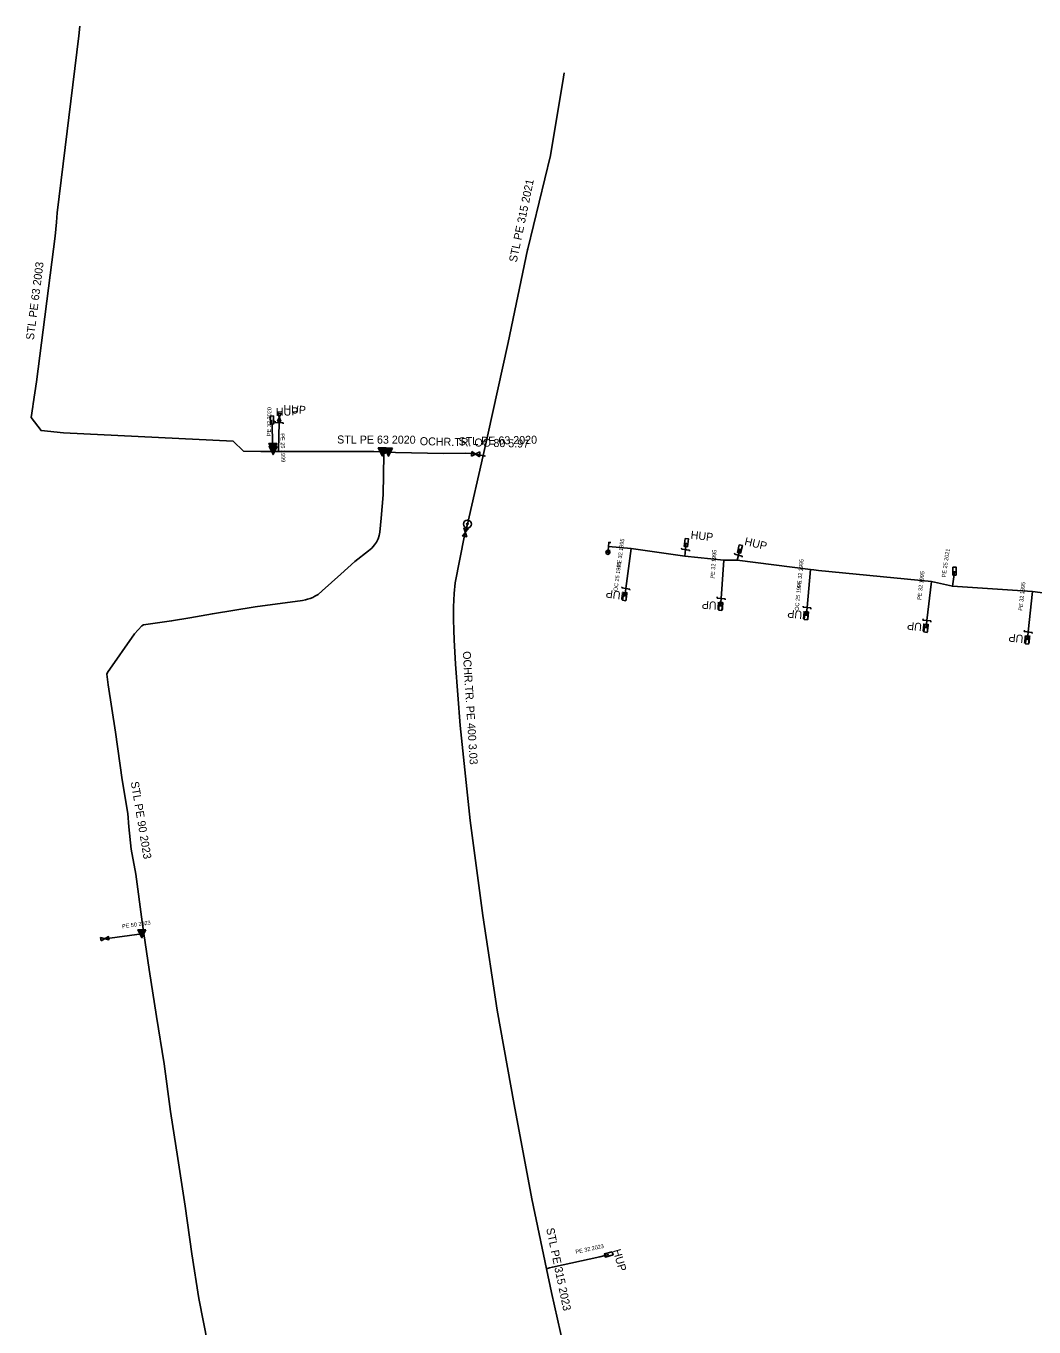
# Model space of a CAD drawing. Extents: x -745298 to -745026, y -1052719 to -1052281.
# Drawn here: x -745298.2 to -745172.2, y -1052443.7 to -1052281.1 of the extents above; entities that cross this region are included whole.
import ezdxf

# ---------------------------------------------------------------- set-up
doc = ezdxf.new("R2010")
doc.units = 0
for name, color, linetype in [('ST OP Chráni_ka - provoz', 7, 'Continuous'), ('ST Úsek p_ípojky - provoz', 7, 'Continuous'), ('ST Úsek plynovodu - provoz', 7, 'Continuous'), ('ST_HUP_22_23_popis', 7, 'Continuous'), ('ST_HUP_24_popis', 7, 'Continuous'), ('Vrstva 1', 7, 'Continuous')]:
    doc.layers.add(name, color=color, linetype=linetype)

msp = doc.modelspace()

# ---------------------------------------------------------------- linework, layer by layer
at = {"layer": 'ST OP Chráni_ka - provoz'}
for points in [[(-745264.93, -1052334.28), (-745254.68, -1052334.31)], [(-745251.97, -1052334.42), (-745246, -1052334.56)], [(-745244.67, -1052357.82), (-745244.48, -1052360.84)]]:
    msp.add_lwpolyline(points, dxfattribs=at)
at = {"layer": 'ST Úsek p_ípojky - provoz'}
for points in [[(-745267.31, -1052333.78), (-745267.43, -1052330.35)], [(-745266.6, -1052334.08), (-745266.54, -1052330.68), (-745266.54, -1052330.67)], [(-745266.54, -1052330.67), (-745266.51, -1052329.99)], [(-745267.29, -1052334.18), (-745267.31, -1052333.88), (-745267.31, -1052333.78)], [(-745266.61, -1052334.28), (-745266.6, -1052334.08)], [(-745267.29, -1052334.29), (-745267.29, -1052334.18)], [(-745222.53, -1052346.42), (-745223.2, -1052351.4)], [(-745215.82, -1052347.37), (-745215.73, -1052346.55)], [(-745215.73, -1052346.55), (-745215.63, -1052345.68)], [(-745209.11, -1052347.24), (-745208.93, -1052346.46)], [(-745210.94, -1052347.85), (-745211.28, -1052352.64)], [(-745209.26, -1052347.86), (-745209.11, -1052347.24)], [(-745200.09, -1052349.05), (-745200.54, -1052353.8)], [(-745182.37, -1052351.12), (-745182.11, -1052349.36), (-745182.11, -1052349.23)], [(-745223.2, -1052351.4), (-745223.33, -1052352.41)], [(-745184.99, -1052350.52), (-745185.56, -1052355.4)], [(-745172.36, -1052351.77), (-745172.89, -1052356.83)], [(-745211.28, -1052352.64), (-745211.35, -1052353.63)], [(-745200.54, -1052353.8), (-745200.64, -1052354.81)], [(-745185.56, -1052355.4), (-745185.67, -1052356.37)], [(-745172.89, -1052356.83), (-745172.99, -1052357.83)], [(-745283.69, -1052394.54), (-745288.32, -1052395.16)], [(-745283.43, -1052394.51), (-745283.69, -1052394.54)], [(-745233.12, -1052436.41), (-745232.75, -1052436.29), (-745232.36, -1052436.19), (-745226.44, -1052434.92), (-745225.32, -1052434.6)]]:
    msp.add_lwpolyline(points, dxfattribs=at)
at = {"layer": 'ST Úsek plynovodu - provoz'}
for points in [[(-745268.82, -1052334.29), (-745270.98, -1052334.26), (-745272.26, -1052333.01), (-745293.47, -1052331.95), (-745296.28, -1052331.68), (-745297.54, -1052330.05), (-745297.33, -1052328.67), (-745297.28, -1052328.34), (-745296.85, -1052325.57), (-745294.54, -1052307.4), (-745294.35, -1052305.63), (-745294.27, -1052304.46), (-745291.55, -1052282.34), (-745291.44, -1052281.13)], [(-745241.04, -1052334.8), (-745240.48, -1052332.37), (-745237.9, -1052320.69), (-745235.48, -1052309.11), (-745235.45, -1052308.96), (-745232.61, -1052297.3), (-745230.97, -1052287.5), (-745230.9, -1052286.99)], [(-745253.25, -1052334.36), (-745253.26, -1052334.51), (-745253.44, -1052334.5), (-745253.45, -1052334.66), (-745253.51, -1052339.72), (-745253.79, -1052342.6), (-745253.93, -1052344.36), (-745254.03, -1052344.8), (-745254.17, -1052345.19), (-745254.37, -1052345.6), (-745254.6, -1052345.96), (-745254.96, -1052346.36), (-745255.34, -1052346.69), (-745257.06, -1052348.03), (-745258.82, -1052349.61), (-745261.15, -1052351.7), (-745261.66, -1052352.16), (-745262.05, -1052352.38), (-745262.33, -1052352.51), (-745262.64, -1052352.64), (-745262.97, -1052352.75), (-745263.25, -1052352.83), (-745263.63, -1052352.91), (-745269.51, -1052353.68), (-745274.86, -1052354.57), (-745277.68, -1052355.06), (-745279.97, -1052355.45), (-745283.5, -1052355.96), (-745283.7, -1052356.07), (-745284.59, -1052357.05), (-745287.99, -1052361.9), (-745288.06, -1052362.12), (-745287.89, -1052363.44), (-745286.97, -1052369.37), (-745286.14, -1052375.3), (-745285.43, -1052379.52), (-745285.31, -1052381.2), (-745285.04, -1052383.96), (-745284.46, -1052387.11), (-745283.65, -1052393.06), (-745283.43, -1052394.51), (-745282.77, -1052398.99), (-745281.86, -1052404.89), (-745280.92, -1052410.81), (-745280.13, -1052416.75), (-745279.18, -1052422.64), (-745278.28, -1052428.58), (-745277.45, -1052434.53), (-745276.55, -1052440.11)], [(-745268.82, -1052334.29), (-745267.29, -1052334.29), (-745267.11, -1052334.29)], [(-745267.11, -1052334.29), (-745266.61, -1052334.28), (-745266.11, -1052334.27)], [(-745266.11, -1052334.27), (-745265.55, -1052334.27), (-745264.93, -1052334.28)], [(-745264.93, -1052334.28), (-745254.68, -1052334.31), (-745253.64, -1052334.35)], [(-745253.64, -1052334.35), (-745253.25, -1052334.36)], [(-745252.87, -1052334.38), (-745253.25, -1052334.36)], [(-745252.87, -1052334.38), (-745251.97, -1052334.42), (-745246, -1052334.56)], [(-745246, -1052334.56), (-745243.2, -1052334.5), (-745242.54, -1052334.55), (-745242.14, -1052334.6)], [(-745243, -1052343.36), (-745241.04, -1052334.8)], [(-745241.95, -1052334.61), (-745242.14, -1052334.6)], [(-745241.04, -1052334.8), (-745240.79, -1052334.86), (-745241.95, -1052334.61)], [(-745243.25, -1052344.39), (-745243.16, -1052343.98), (-745243, -1052343.36)], [(-745243.25, -1052344.39), (-745243.34, -1052344.8), (-745244.53, -1052350.7), (-745244.64, -1052352.05), (-745244.72, -1052353.69), (-745244.73, -1052355.27), (-745244.7, -1052356.6), (-745244.67, -1052357.82), (-745244.48, -1052360.84), (-745243.89, -1052368.52), (-745242.66, -1052380.39), (-745241.08, -1052392.25), (-745239.28, -1052404.11), (-745237.17, -1052415.89), (-745234.95, -1052427.66), (-745233.12, -1052436.41), (-745232.48, -1052439.35), (-745229.87, -1052451.04)], [(-745225.37, -1052346.14), (-745222.53, -1052346.42), (-745215.82, -1052347.37), (-745210.94, -1052347.85), (-745209.26, -1052347.86), (-745200.09, -1052349.05), (-745199.68, -1052349.09), (-745199.09, -1052349.15), (-745184.99, -1052350.52), (-745182.37, -1052351.12), (-745172.36, -1052351.77), (-745166.25, -1052352.58)], [(-745276.55, -1052440.11), (-745275.46, -1052445.8), (-745274.94, -1052448.81), (-745274.89, -1052449.09), (-745274.33, -1052451.51), (-745274.28, -1052451.72)]]:
    msp.add_lwpolyline(points, dxfattribs=at)
at = {"layer": 'Vrstva 1'}
for p, q in [((-745267.04, -1052330.65), (-745267.03, -1052330.5)), ((-745267.04, -1052330.65), (-745266.04, -1052330.69)), ((-745266.04, -1052330.69), (-745266.04, -1052330.84)), ((-745242.47, -1052334.88), (-745242.43, -1052334.28)), ((-745241.43, -1052334.34), (-745242.47, -1052334.88)), ((-745242.43, -1052334.28), (-745241.47, -1052334.94)), ((-745241.47, -1052334.94), (-745241.43, -1052334.34)), ((-745243.44, -1052343.84), (-745242.85, -1052343.97)), ((-745243.06, -1052344.94), (-745243.44, -1052343.84)), ((-745242.85, -1052343.97), (-745243.65, -1052344.81)), ((-745243.65, -1052344.81), (-745243.06, -1052344.94)), ((-745225.37, -1052346.14), (-745225.42, -1052346.64)), ((-745216.22, -1052346.5), (-745216.21, -1052346.35)), ((-745215.23, -1052346.61), (-745216.22, -1052346.5)), ((-745215.23, -1052346.61), (-745215.25, -1052346.76)), ((-745209.6, -1052347.13), (-745209.57, -1052346.98)), ((-745208.63, -1052347.35), (-745209.6, -1052347.13)), ((-745208.63, -1052347.35), (-745208.66, -1052347.5)), ((-745223.69, -1052351.34), (-745223.67, -1052351.19)), ((-745223.69, -1052351.34), (-745222.7, -1052351.47)), ((-745222.7, -1052351.47), (-745222.72, -1052351.62)), ((-745211.78, -1052352.61), (-745211.77, -1052352.46)), ((-745210.78, -1052352.68), (-745211.78, -1052352.61)), ((-745210.78, -1052352.68), (-745210.79, -1052352.83)), ((-745201.04, -1052353.75), (-745201.03, -1052353.6)), ((-745201.04, -1052353.75), (-745200.05, -1052353.84)), ((-745200.05, -1052353.84), (-745200.06, -1052353.99)), ((-745186.05, -1052355.35), (-745186.04, -1052355.2)), ((-745186.05, -1052355.35), (-745185.06, -1052355.46)), ((-745185.06, -1052355.46), (-745185.08, -1052355.61)), ((-745173.38, -1052356.78), (-745173.37, -1052356.63)), ((-745173.38, -1052356.78), (-745172.39, -1052356.89)), ((-745172.39, -1052356.89), (-745172.4, -1052357.03))]:
    msp.add_line(p, q, dxfattribs=at)
for points in [[(-745267.64, -1052329.86), (-745267.24, -1052329.85), (-745267.21, -1052330.85), (-745267.61, -1052330.86)], [(-745266.81, -1052333.28), (-745267.81, -1052333.28), (-745267.31, -1052334.28)], [(-745266.79, -1052333.68), (-745267.79, -1052333.68), (-745267.29, -1052334.68)], [(-745267.65, -1052333.38), (-745267.31, -1052334.05), (-745266.97, -1052333.38)], [(-745267.63, -1052333.78), (-745267.29, -1052334.46), (-745266.95, -1052333.78)], [(-745267.31, -1052333.83), (-745267.14, -1052333.48), (-745267.49, -1052333.48)], [(-745267.29, -1052334.23), (-745267.11, -1052333.88), (-745267.47, -1052333.88)], [(-745253.14, -1052333.85), (-745254.14, -1052333.85), (-745253.64, -1052334.85)], [(-745253.98, -1052333.95), (-745253.64, -1052334.62), (-745253.3, -1052333.95)], [(-745253.64, -1052334.4), (-745253.47, -1052334.05), (-745253.82, -1052334.05)], [(-745252.37, -1052333.88), (-745253.37, -1052333.88), (-745252.87, -1052334.88)], [(-745253.2, -1052333.98), (-745252.87, -1052334.65), (-745252.53, -1052333.98)], [(-745252.87, -1052334.43), (-745252.69, -1052334.08), (-745253.04, -1052334.08)], [(-745242.91, -1052343.3), (-745242.95, -1052343.45), (-745243.09, -1052343.42), (-745243.05, -1052343.27)], [(-745215.77, -1052345.16), (-745215.37, -1052345.2), (-745215.49, -1052346.2), (-745215.88, -1052346.15)], [(-745209.01, -1052345.93), (-745208.62, -1052346.02), (-745208.85, -1052346.99), (-745209.24, -1052346.9)], [(-745182.31, -1052348.73), (-745181.91, -1052348.73), (-745181.91, -1052349.73), (-745182.31, -1052349.73)], [(-745223.2, -1052352.93), (-745223.59, -1052352.88), (-745223.46, -1052351.89), (-745223.07, -1052351.94)], [(-745211.18, -1052354.14), (-745211.58, -1052354.11), (-745211.51, -1052353.12), (-745211.11, -1052353.14)], [(-745200.49, -1052355.33), (-745200.88, -1052355.29), (-745200.79, -1052354.29), (-745200.39, -1052354.33)], [(-745185.53, -1052356.89), (-745185.93, -1052356.84), (-745185.81, -1052355.85), (-745185.41, -1052355.89)], [(-745172.84, -1052358.35), (-745173.24, -1052358.3), (-745173.14, -1052357.31), (-745172.74, -1052357.35)], [(-745283.19, -1052394.04), (-745284.19, -1052394.04), (-745283.69, -1052395.04)], [(-745284.03, -1052394.14), (-745283.69, -1052394.82), (-745283.35, -1052394.14)], [(-745283.69, -1052394.6), (-745283.52, -1052394.24), (-745283.87, -1052394.24)], [(-745224.89, -1052434.27), (-745224.78, -1052434.65), (-745225.75, -1052434.93), (-745225.86, -1052434.55)]]:
    msp.add_lwpolyline(points, close=True, dxfattribs=at)
for points in [[(-745266.69, -1052329.48), (-745266.29, -1052329.5), (-745266.73, -1052330.48), (-745266.33, -1052330.5), (-745266.69, -1052329.48)], [(-745225.17, -1052346.66), (-745225.42, -1052346.64), (-745225.32, -1052345.64), (-745225.07, -1052345.67)], [(-745288.79, -1052395.42), (-745288.84, -1052395.03), (-745287.8, -1052395.29), (-745287.85, -1052394.9), (-745288.79, -1052395.42)]]:
    msp.add_lwpolyline(points, dxfattribs=at)
for centre, radius in [((-745243, -1052343.36), 0.5), ((-745225.44, -1052346.89), 0.249), ((-745225.54, -1052346.86), 0.0614), ((-745225.33, -1052346.88), 0.0614)]:
    msp.add_circle(centre, radius, dxfattribs=at)

# ---------------------------------------------------------------- texts
at = {"layer": 'ST OP Chráni_ka - provoz'}
for s, rotation, p in [('OCHR.TR. OC 80 5.97', 358.6276, (-745248.96, -1052333.49)), ('OCHR.TR. PE 400 3.03', 273.6, (-745243.58, -1052359.27))]:
    msp.add_text(s, height=1, rotation=rotation, dxfattribs=at).set_placement(p)
at = {"layer": 'ST Úsek p_ípojky - provoz'}
for s, rotation, p in [('PE 32 2020', 88.8367, (-745267.57, -1052332.36)), ('PE 25 1999', 271.9242, (-745266.37, -1052332.03)), ('PE 32 1995', 82.3986, (-745223.85, -1052348.78)), ('PE 32 1995', 85.9424, (-745212.11, -1052350.18)), ('PE 25 2021', 81.5966, (-745183.22, -1052350.03)), ('OC 25 1995', 82.3493, (-745224.25, -1052351.77)), ('PE 32 1995', 84.5488, (-745201.31, -1052351.33)), ('PE 32 1995', 83.3896, (-745186.27, -1052352.85)), ('OC 25 1995', 84.6424, (-745201.59, -1052354.21)), ('PE 32 1995', 84.0811, (-745173.62, -1052354.2)), ('PE 50 2023', 7.5955, (-745286.14, -1052393.86)), ('PE 32 2023', 12.108, (-745229.43, -1052434.54))]:
    msp.add_text(s, height=0.5, rotation=rotation, dxfattribs=at).set_placement(p)
at = {"layer": 'ST Úsek plynovodu - provoz'}
for s, rotation, p in [('STL PE 315 2021', 78.1962, (-745236.84, -1052310.71)), ('STL PE 63 2003', 82.7547, (-745297.2, -1052320.4)), ('STL PE 63 2020', 359.8491, (-745259.28, -1052333.29)), ('STL PE 63 2020', 1.2276, (-745244.09, -1052333.52)), ('STL PE 90 2023', 279.5504, (-745285.08, -1052375.59)), ('STL PE 315 2023', 281.8127, (-745233.15, -1052431.39))]:
    msp.add_text(s, height=1, rotation=rotation, dxfattribs=at).set_placement(p)
at = {"layer": 'ST_HUP_22_23_popis'}
for rotation, p in [(1.92, (-745266.93, -1052329.85)), (353.55, (-745215.13, -1052345.18)), (346.53, (-745208.43, -1052345.96)), (172.35, (-745222.83, -1052351.91)), (176.05, (-745210.85, -1052353.13)), (174.64, (-745200.14, -1052354.31)), (173.26, (-745185.17, -1052355.87)), (174.08, (-745172.49, -1052357.33)), (285.95, (-745224.82, -1052434.1))]:
    msp.add_text('HUP', height=1, rotation=rotation, dxfattribs=at).set_placement(p)
at = {"layer": 'ST_HUP_24_popis'}
msp.add_text('HUP', height=1, rotation=357.74, dxfattribs=at).set_placement((-745266.01, -1052329.49))

doc.saveas('drawing.dxf')
